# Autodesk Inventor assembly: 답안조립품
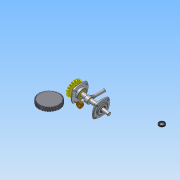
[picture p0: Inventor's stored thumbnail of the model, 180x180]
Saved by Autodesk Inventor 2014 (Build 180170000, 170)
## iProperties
Created: 2016-05
Part Number: 답안조립품
Document SubType Name: Assembly
Designer: Administrator
Author: Administrator
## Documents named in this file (12)
- C:\Users\Administrator\Desktop\460507V1001\답안조립품.iam
- C:\Users\Administrator\Desktop\460507V1001\M4x0.7x12.ipt
- C:\Users\Administrator\Desktop\460507V1001\베어링-6203.ipt
- C:\Users\Administrator\Desktop\460507V1001\본체.ipt
- C:\Users\Administrator\Desktop\460507V1001\부시.ipt
- C:\Users\Administrator\Desktop\460507V1001\스퍼기어.ipt
- C:\Users\Administrator\Desktop\460507V1001\스프로킷.ipt
- C:\Users\Administrator\Desktop\460507V1001\슬라이더.ipt
- C:\Users\Administrator\Desktop\460507V1001\오일실.ipt
- C:\Users\Administrator\Desktop\460507V1001\커버.ipt
- C:\Users\Administrator\Desktop\460507V1001\키5x5.ipt
- C:\Users\Administrator\Desktop\460507V1001\편심축.ipt
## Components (8 placed, 1 different names)
1. M4x0.7x12:1
2. M4x0.7x12:2
3. M4x0.7x12:3
4. M4x0.7x12:4
5. M4x0.7x12:5
6. M4x0.7x12:6
7. M4x0.7x12:7
8. M4x0.7x12:8
## Named parameters: d9_d7 = 0, d10_d8 = 0, d14_d9_d7 = 0, d15_d10_d8 = 0, d16_d12 = 0, d17_d13 = 0
